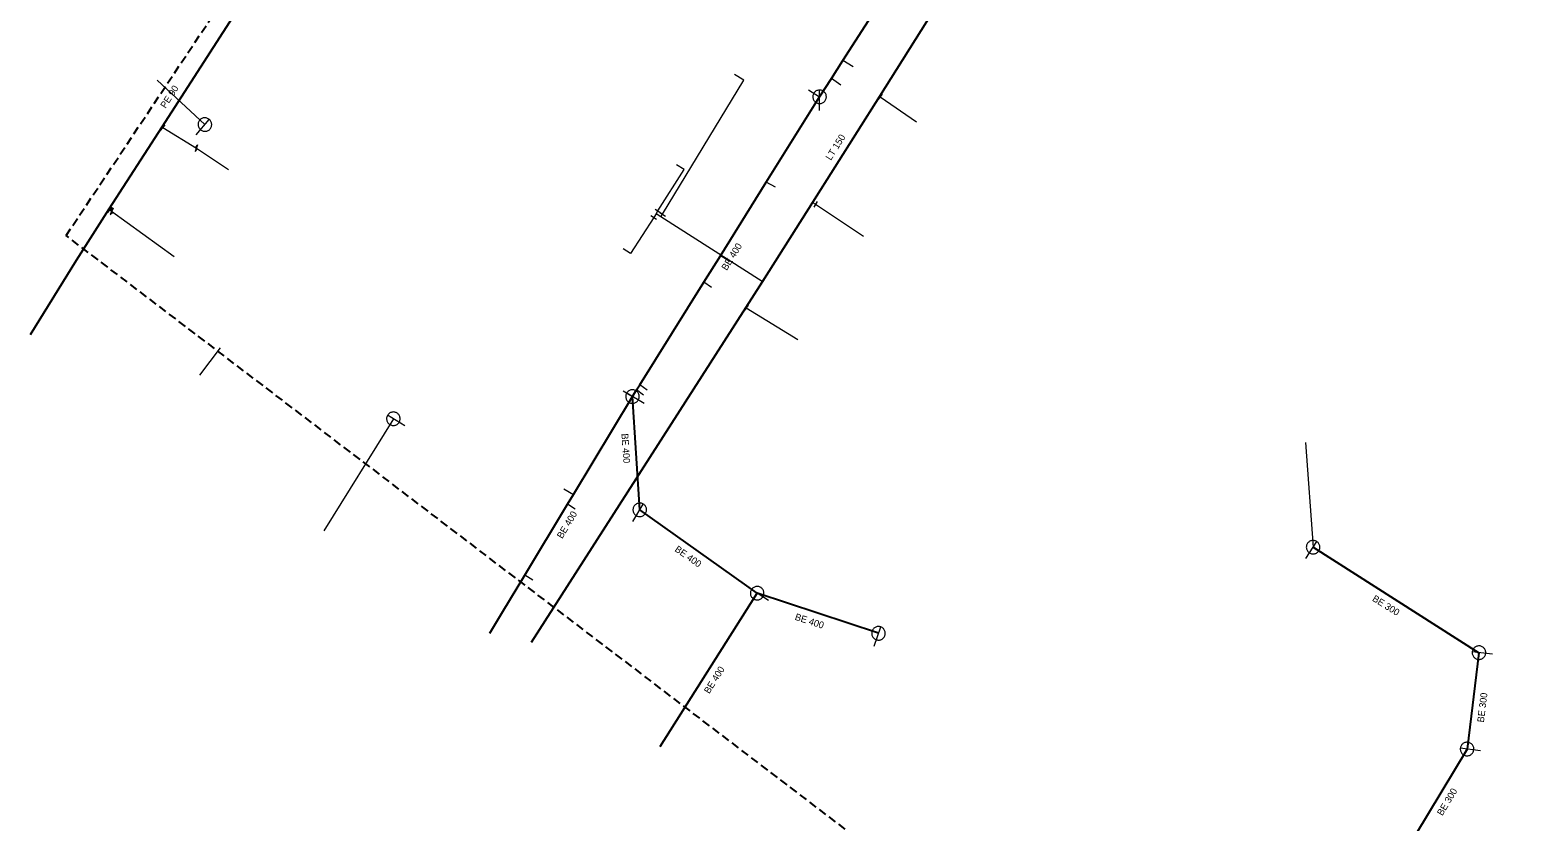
# Model space of a CAD drawing. Extents: x -791337 to -790755, y -988454 to -987923.
# Drawn here: x -791336.8 to -791114.4, y -988160.4 to -988043.6 of the extents above; entities that cross this region are included whole.
import ezdxf

# ---------------------------------------------------------------- set-up
doc = ezdxf.new("R2010")
doc.units = 0
doc.header["$LTSCALE"] = 0.4
doc.linetypes.add('MEDIUM_DASHED', pattern=[4.5, 3, -1.5])
for name, color, linetype, lineweight in [('1', 7, 'Continuous', 13), ('11', 7, 'Continuous', 13), ('13', 7, 'Continuous', 13), ('14', 7, 'Continuous', 25), ('17', 7, 'Continuous', 25), ('22', 7, 'Continuous', 13), ('34', 7, 'Continuous', 13), ('47', 7, 'Continuous', 13), ('63', 7, 'MEDIUM_DASHED', 25)]:
    doc.layers.add(name, color=color, linetype=linetype, lineweight=lineweight)

msp = doc.modelspace()

# ---------------------------------------------------------------- linework, layer by layer
at = {"layer": '11'}
for p, q in [((-791215.394, -988048.979), (-791216.914, -988048.035)), ((-791311.03, -988057.489), (-791318.067, -988050.953)), ((-791217.249, -988051.696), (-791218.616, -988050.685)), ((-791221.997, -988052.379), (-791220.36, -988053.399)), ((-791226.844, -988066.741), (-791228.219, -988065.989)), ((-791233.621, -988077.693), (-791234.99, -988076.837)), ((-791236.314, -988081.552), (-791237.428, -988080.744)), ((-791308.761, -988090.436), (-791311.837, -988094.46)), ((-791245.784, -988096.678), (-791246.89, -988095.902)), ((-791249.33, -988096.767), (-791247.96, -988097.618)), ((-791246.323, -988097.396), (-791247.349, -988096.637)), ((-791283.232, -988100.901), (-791293.503, -988117.455)), ((-791148.662, -988104.384), (-791147.564, -988119.853)), ((-791258.082, -988111.264), (-791256.681, -988112.097)), ((-791256.421, -988114.227), (-791257.529, -988113.506)), ((-791262.66, -988124.729), (-791263.835, -988123.978))]:
    msp.add_line(p, q, dxfattribs=at)
at = {"layer": '13'}
for p, q in [((-791211.439, -988053.409), (-791206.055, -988057.074)), ((-791220.971, -988069.259), (-791213.883, -988073.951)), ((-791244.489, -988070.666), (-791244.206, -988070.226)), ((-791231.17, -988084.549), (-791223.563, -988089.212))]:
    msp.add_line(p, q, dxfattribs=at)
for points in [[(-791243.519, -988070.729), (-791231.521, -988050.931), (-791232.905, -988050.09)], [(-791317.379, -988057.85), (-791317.26, -988057.94), (-791312.28, -988060.969), (-791307.574, -988064.107)], [(-791244.206, -988070.226), (-791240.35, -988064.101), (-791241.451, -988063.407)], [(-791325.199, -988069.989), (-791325.079, -988070.079), (-791324.794, -988070.282), (-791315.569, -988076.949)], [(-791244.831, -988071.195), (-791248.272, -988076.535), (-791249.34, -988075.846)], [(-791228.84, -988080.629), (-791243.759, -988071.116), (-791244.489, -988070.666), (-791244.831, -988071.195)]]:
    msp.add_lwpolyline(points, dxfattribs=at)
at = {"layer": '14', "lineweight": 13}
for p, q in [((-791211.533, -988053.348), (-791211.439, -988053.409)), ((-791221.417, -988069.009), (-791220.971, -988069.259)), ((-791243.759, -988071.116), (-791243.519, -988070.729)), ((-791228.785, -988080.667), (-791228.84, -988080.629)), ((-791231.254, -988084.482), (-791231.17, -988084.549))]:
    msp.add_line(p, q, dxfattribs=at)
at = {"layer": '14'}
for p, q in [((-791147.564, -988119.853), (-791123.093, -988135.415)), ((-791243.863, -988149.281), (-791229.566, -988126.639)), ((-791211.664, -988132.557), (-791229.566, -988126.639)), ((-791123.093, -988135.415), (-791124.854, -988149.635)), ((-791124.854, -988149.635), (-791132.46, -988162.294))]:
    msp.add_line(p, q, dxfattribs=at)
for points in [[(-791220.36, -988053.399), (-791218.616, -988050.685), (-791216.914, -988048.035), (-791206.587, -988031.96), (-791205.24, -988029.863), (-791199.047, -988020.224), (-791197.614, -988017.994), (-791194.219, -988012.71)], [(-791247.96, -988097.618), (-791247.349, -988096.637), (-791246.89, -988095.902), (-791237.428, -988080.744), (-791234.99, -988076.837), (-791228.219, -988065.989), (-791220.36, -988053.399)], [(-791268.993, -988132.543), (-791267.076, -988129.358), (-791263.835, -988123.978), (-791257.529, -988113.506), (-791256.681, -988112.097), (-791247.96, -988097.618)], [(-791229.566, -988126.639), (-791246.888, -988114.339), (-791247.96, -988097.618)]]:
    msp.add_lwpolyline(points, dxfattribs=at)
at = {"layer": '17'}
for points in [[(-791185.71, -988012.8), (-791199.495, -988034.364), (-791203.749, -988041.021), (-791211.533, -988053.348), (-791221.416, -988069.009), (-791228.785, -988080.667), (-791231.254, -988084.482), (-791262.91, -988133.899)], [(-791304.129, -988037.219), (-791317.379, -988057.85), (-791325.199, -988069.989), (-791330.01, -988077.55), (-791336.809, -988088.51)]]:
    msp.add_lwpolyline(points, dxfattribs=at)
at = {"layer": '22'}
for p, q in [((-791220.36, -988055.399), (-791220.359, -988052.399)), ((-791312.332, -988059.007), (-791310.379, -988056.73)), ((-791246.246, -988098.65), (-791248.816, -988097.102)), ((-791281.526, -988101.947), (-791284.083, -988100.378)), ((-791247.907, -988116.06), (-791246.378, -988113.478)), ((-791148.637, -988121.541), (-791147.027, -988119.009)), ((-791227.874, -988127.707), (-791230.411, -988126.105)), ((-791212.291, -988134.456), (-791211.35, -988131.608)), ((-791121.107, -988135.66), (-791124.084, -988135.292)), ((-791122.868, -988149.88), (-791125.845, -988149.512))]:
    msp.add_line(p, q, dxfattribs=at)
for points in [[(-791219.36, -988053.399), (-791219.365, -988053.29), (-791219.383, -988053.182), (-791219.413, -988053.076), (-791219.453, -988052.975), (-791219.505, -988052.878), (-791219.567, -988052.788), (-791219.639, -988052.705), (-791219.719, -988052.631), (-791219.807, -988052.565), (-791219.901, -988052.51), (-791220.001, -988052.465), (-791220.106, -988052.432), (-791220.213, -988052.41), (-791220.322, -988052.4), (-791220.432, -988052.402), (-791220.54, -988052.416), (-791220.647, -988052.441), (-791220.75, -988052.478), (-791220.848, -988052.527), (-791220.94, -988052.585), (-791221.026, -988052.654), (-791221.103, -988052.731), (-791221.172, -988052.817), (-791221.231, -988052.909), (-791221.279, -988053.007), (-791221.316, -988053.11), (-791221.342, -988053.217), (-791221.356, -988053.325), (-791221.359, -988053.435), (-791221.349, -988053.544), (-791221.328, -988053.651), (-791221.294, -988053.755), (-791221.25, -988053.855), (-791221.195, -988053.95), (-791221.129, -988054.038), (-791221.055, -988054.118), (-791220.972, -988054.19), (-791220.882, -988054.252), (-791220.786, -988054.304), (-791220.684, -988054.345), (-791220.579, -988054.375), (-791220.471, -988054.393), (-791220.361, -988054.399), (-791220.252, -988054.393), (-791220.144, -988054.375), (-791220.039, -988054.346), (-791219.937, -988054.305), (-791219.84, -988054.253), (-791219.75, -988054.191), (-791219.667, -988054.12), (-791219.592, -988054.04), (-791219.527, -988053.952), (-791219.471, -988053.858), (-791219.427, -988053.758), (-791219.393, -988053.654), (-791219.371, -988053.546), (-791219.361, -988053.437)], [(-791310.271, -988058.14), (-791310.204, -988058.053), (-791310.148, -988057.96), (-791310.101, -988057.86), (-791310.066, -988057.757), (-791310.042, -988057.649), (-791310.031, -988057.541), (-791310.031, -988057.431), (-791310.044, -988057.323), (-791310.068, -988057.215), (-791310.103, -988057.112), (-791310.15, -988057.013), (-791310.208, -988056.92), (-791310.275, -988056.833), (-791310.351, -988056.755), (-791310.436, -988056.685), (-791310.527, -988056.625), (-791310.625, -988056.574), (-791310.727, -988056.535), (-791310.833, -988056.509), (-791310.941, -988056.493), (-791311.051, -988056.489), (-791311.16, -988056.497), (-791311.268, -988056.518), (-791311.373, -988056.549), (-791311.473, -988056.592), (-791311.568, -988056.646), (-791311.658, -988056.711), (-791311.738, -988056.784), (-791311.812, -988056.866), (-791311.875, -988056.955), (-791311.929, -988057.05), (-791311.971, -988057.151), (-791312.002, -988057.256), (-791312.022, -988057.364), (-791312.03, -988057.473), (-791312.025, -988057.582), (-791312.009, -988057.691), (-791311.981, -988057.797), (-791311.942, -988057.899), (-791311.892, -988057.996), (-791311.831, -988058.087), (-791311.761, -988058.171), (-791311.682, -988058.247), (-791311.595, -988058.314), (-791311.501, -988058.37), (-791311.403, -988058.417), (-791311.299, -988058.452), (-791311.191, -988058.476), (-791311.082, -988058.487), (-791310.973, -988058.487), (-791310.864, -988058.475), (-791310.758, -988058.451), (-791310.654, -988058.416), (-791310.555, -988058.369), (-791310.462, -988058.312), (-791310.375, -988058.244), (-791310.296, -988058.168)], [(-791247.443, -988096.761), (-791247.54, -988096.71), (-791247.641, -988096.67), (-791247.748, -988096.641), (-791247.855, -988096.623), (-791247.965, -988096.617), (-791248.074, -988096.624), (-791248.182, -988096.643), (-791248.287, -988096.673), (-791248.389, -988096.715), (-791248.484, -988096.767), (-791248.574, -988096.829), (-791248.657, -988096.902), (-791248.731, -988096.982), (-791248.796, -988097.071), (-791248.851, -988097.166), (-791248.895, -988097.266), (-791248.928, -988097.37), (-791248.95, -988097.478), (-791248.958, -988097.587), (-791248.956, -988097.696), (-791248.941, -988097.805), (-791248.915, -988097.91), (-791248.877, -988098.014), (-791248.829, -988098.112), (-791248.77, -988098.204), (-791248.7, -988098.288), (-791248.622, -988098.366), (-791248.537, -988098.434), (-791248.444, -988098.492), (-791248.345, -988098.54), (-791248.243, -988098.577), (-791248.136, -988098.602), (-791248.028, -988098.615), (-791247.918, -988098.617), (-791247.808, -988098.606), (-791247.702, -988098.584), (-791247.597, -988098.55), (-791247.498, -988098.505), (-791247.404, -988098.45), (-791247.316, -988098.383), (-791247.236, -988098.309), (-791247.165, -988098.226), (-791247.103, -988098.135), (-791247.052, -988098.038), (-791247.012, -988097.936), (-791246.982, -988097.831), (-791246.965, -988097.723), (-791246.959, -988097.613), (-791246.966, -988097.504), (-791246.984, -988097.396), (-791247.014, -988097.291), (-791247.056, -988097.189), (-791247.107, -988097.093), (-791247.17, -988097.004), (-791247.242, -988096.921), (-791247.323, -988096.846), (-791247.411, -988096.782)], [(-791282.708, -988100.048), (-791282.804, -988099.997), (-791282.906, -988099.955), (-791283.012, -988099.926), (-791283.119, -988099.907), (-791283.228, -988099.9), (-791283.338, -988099.906), (-791283.446, -988099.924), (-791283.551, -988099.954), (-791283.653, -988099.994), (-791283.749, -988100.045), (-791283.84, -988100.107), (-791283.923, -988100.179), (-791283.998, -988100.259), (-791284.063, -988100.347), (-791284.119, -988100.441), (-791284.164, -988100.541), (-791284.198, -988100.645), (-791284.221, -988100.752), (-791284.23, -988100.861), (-791284.229, -988100.97), (-791284.215, -988101.08), (-791284.19, -988101.185), (-791284.152, -988101.289), (-791284.105, -988101.388), (-791284.046, -988101.48), (-791283.978, -988101.565), (-791283.9, -988101.643), (-791283.816, -988101.712), (-791283.723, -988101.771), (-791283.625, -988101.82), (-791283.523, -988101.858), (-791283.416, -988101.883), (-791283.308, -988101.898), (-791283.198, -988101.901), (-791283.089, -988101.89), (-791282.982, -988101.869), (-791282.877, -988101.836), (-791282.777, -988101.792), (-791282.683, -988101.737), (-791282.594, -988101.672), (-791282.514, -988101.598), (-791282.442, -988101.515), (-791282.379, -988101.425), (-791282.327, -988101.329), (-791282.286, -988101.227), (-791282.256, -988101.123), (-791282.238, -988101.014), (-791282.231, -988100.904), (-791282.237, -988100.795), (-791282.254, -988100.687), (-791282.283, -988100.581), (-791282.324, -988100.48), (-791282.375, -988100.383), (-791282.437, -988100.293), (-791282.508, -988100.21), (-791282.588, -988100.135), (-791282.676, -988100.069)], [(-791246.027, -988114.848), (-791245.977, -988114.752), (-791245.937, -988114.65), (-791245.909, -988114.543), (-791245.892, -988114.436), (-791245.887, -988114.326), (-791245.895, -988114.217), (-791245.915, -988114.109), (-791245.946, -988114.004), (-791245.988, -988113.903), (-791246.041, -988113.807), (-791246.104, -988113.718), (-791246.177, -988113.636), (-791246.258, -988113.562), (-791246.347, -988113.498), (-791246.443, -988113.444), (-791246.543, -988113.401), (-791246.647, -988113.368), (-791246.755, -988113.347), (-791246.864, -988113.339), (-791246.973, -988113.342), (-791247.082, -988113.358), (-791247.188, -988113.385), (-791247.291, -988113.424), (-791247.388, -988113.473), (-791247.48, -988113.533), (-791247.564, -988113.603), (-791247.641, -988113.681), (-791247.708, -988113.767), (-791247.766, -988113.861), (-791247.813, -988113.96), (-791247.849, -988114.063), (-791247.873, -988114.169), (-791247.886, -988114.278), (-791247.887, -988114.388), (-791247.875, -988114.497), (-791247.852, -988114.603), (-791247.817, -988114.708), (-791247.772, -988114.807), (-791247.715, -988114.901), (-791247.649, -988114.988), (-791247.574, -988115.067), (-791247.49, -988115.138), (-791247.398, -988115.199), (-791247.301, -988115.249), (-791247.199, -988115.289), (-791247.094, -988115.317), (-791246.985, -988115.334), (-791246.875, -988115.339), (-791246.766, -988115.331), (-791246.659, -988115.312), (-791246.554, -988115.282), (-791246.453, -988115.239), (-791246.357, -988115.187), (-791246.268, -988115.123), (-791246.186, -988115.051), (-791246.112, -988114.969), (-791246.048, -988114.881)], [(-791146.72, -988120.39), (-791146.667, -988120.294), (-791146.624, -988120.194), (-791146.592, -988120.088), (-791146.572, -988119.981), (-791146.564, -988119.872), (-791146.568, -988119.762), (-791146.584, -988119.654), (-791146.612, -988119.548), (-791146.65, -988119.445), (-791146.7, -988119.349), (-791146.76, -988119.257), (-791146.831, -988119.173), (-791146.91, -988119.097), (-791146.996, -988119.03), (-791147.09, -988118.972), (-791147.189, -988118.926), (-791147.293, -988118.89), (-791147.399, -988118.866), (-791147.508, -988118.855), (-791147.617, -988118.854), (-791147.727, -988118.866), (-791147.833, -988118.89), (-791147.937, -988118.926), (-791148.037, -988118.972), (-791148.13, -988119.028), (-791148.216, -988119.096), (-791148.296, -988119.172), (-791148.365, -988119.255), (-791148.426, -988119.347), (-791148.476, -988119.445), (-791148.516, -988119.546), (-791148.543, -988119.652), (-791148.559, -988119.76), (-791148.564, -988119.87), (-791148.556, -988119.979), (-791148.536, -988120.087), (-791148.505, -988120.192), (-791148.462, -988120.293), (-791148.409, -988120.388), (-791148.345, -988120.477), (-791148.272, -988120.559), (-791148.191, -988120.632), (-791148.101, -988120.696), (-791148.006, -988120.75), (-791147.905, -988120.792), (-791147.801, -988120.824), (-791147.693, -988120.844), (-791147.583, -988120.853), (-791147.474, -988120.849), (-791147.366, -988120.833), (-791147.26, -988120.806), (-791147.158, -988120.767), (-791147.06, -988120.717), (-791146.969, -988120.657), (-791146.885, -988120.587), (-791146.808, -988120.508), (-791146.741, -988120.421)], [(-791229.031, -988125.793), (-791229.127, -988125.74), (-791229.227, -988125.698), (-791229.333, -988125.666), (-791229.44, -988125.646), (-791229.55, -988125.639), (-791229.659, -988125.643), (-791229.767, -988125.659), (-791229.873, -988125.688), (-791229.976, -988125.727), (-791230.072, -988125.777), (-791230.164, -988125.837), (-791230.248, -988125.909), (-791230.323, -988125.987), (-791230.39, -988126.074), (-791230.447, -988126.168), (-791230.493, -988126.267), (-791230.529, -988126.371), (-791230.553, -988126.478), (-791230.563, -988126.587), (-791230.564, -988126.695), (-791230.551, -988126.805), (-791230.527, -988126.911), (-791230.491, -988127.015), (-791230.445, -988127.114), (-791230.388, -988127.207), (-791230.32, -988127.294), (-791230.244, -988127.373), (-791230.16, -988127.442), (-791230.068, -988127.503), (-791229.971, -988127.552), (-791229.869, -988127.592), (-791229.763, -988127.619), (-791229.655, -988127.635), (-791229.545, -988127.639), (-791229.435, -988127.63), (-791229.328, -988127.61), (-791229.223, -988127.579), (-791229.123, -988127.536), (-791229.027, -988127.482), (-791228.938, -988127.418), (-791228.857, -988127.345), (-791228.784, -988127.263), (-791228.72, -988127.174), (-791228.667, -988127.078), (-791228.625, -988126.977), (-791228.593, -988126.873), (-791228.573, -988126.765), (-791228.565, -988126.655), (-791228.57, -988126.546), (-791228.585, -988126.438), (-791228.613, -988126.332), (-791228.653, -988126.23), (-791228.702, -988126.132), (-791228.763, -988126.042), (-791228.833, -988125.957), (-791228.913, -988125.881), (-791229, -988125.814)], [(-791210.714, -988132.871), (-791210.686, -988132.765), (-791210.669, -988132.657), (-791210.664, -988132.547), (-791210.67, -988132.439), (-791210.689, -988132.33), (-791210.72, -988132.225), (-791210.762, -988132.124), (-791210.815, -988132.029), (-791210.878, -988131.938), (-791210.95, -988131.857), (-791211.031, -988131.783), (-791211.12, -988131.718), (-791211.215, -988131.664), (-791211.315, -988131.62), (-791211.42, -988131.587), (-791211.527, -988131.567), (-791211.636, -988131.557), (-791211.746, -988131.56), (-791211.854, -988131.576), (-791211.96, -988131.602), (-791212.063, -988131.64), (-791212.16, -988131.689), (-791212.253, -988131.749), (-791212.338, -988131.818), (-791212.414, -988131.896), (-791212.482, -988131.982), (-791212.54, -988132.076), (-791212.587, -988132.174), (-791212.623, -988132.278), (-791212.648, -988132.384), (-791212.662, -988132.492), (-791212.662, -988132.602), (-791212.652, -988132.711), (-791212.629, -988132.818), (-791212.594, -988132.922), (-791212.549, -988133.021), (-791212.493, -988133.116), (-791212.427, -988133.203), (-791212.352, -988133.283), (-791212.268, -988133.353), (-791212.178, -988133.415), (-791212.081, -988133.466), (-791211.978, -988133.506), (-791211.873, -988133.535), (-791211.765, -988133.551), (-791211.656, -988133.557), (-791211.546, -988133.55), (-791211.438, -988133.531), (-791211.333, -988133.5), (-791211.232, -988133.459), (-791211.136, -988133.407), (-791211.046, -988133.343), (-791210.964, -988133.272), (-791210.89, -988133.191), (-791210.826, -988133.103), (-791210.771, -988133.007), (-791210.727, -988132.907)], [(-791122.969, -988134.422), (-791123.078, -988134.415), (-791123.187, -988134.419), (-791123.296, -988134.436), (-791123.401, -988134.463), (-791123.504, -988134.503), (-791123.601, -988134.553), (-791123.692, -988134.615), (-791123.776, -988134.685), (-791123.852, -988134.764), (-791123.918, -988134.851), (-791123.975, -988134.944), (-791124.021, -988135.045), (-791124.056, -988135.148), (-791124.079, -988135.255), (-791124.09, -988135.364), (-791124.09, -988135.473), (-791124.078, -988135.583), (-791124.054, -988135.689), (-791124.017, -988135.793), (-791123.971, -988135.891), (-791123.913, -988135.985), (-791123.846, -988136.071), (-791123.77, -988136.15), (-791123.685, -988136.22), (-791123.594, -988136.279), (-791123.496, -988136.329), (-791123.393, -988136.368), (-791123.288, -988136.395), (-791123.179, -988136.41), (-791123.07, -988136.414), (-791122.961, -988136.406), (-791122.853, -988136.385), (-791122.749, -988136.354), (-791122.648, -988136.311), (-791122.552, -988136.256), (-791122.464, -988136.193), (-791122.382, -988136.119), (-791122.31, -988136.037), (-791122.246, -988135.949), (-791122.193, -988135.852), (-791122.15, -988135.752), (-791122.119, -988135.647), (-791122.1, -988135.538), (-791122.092, -988135.43), (-791122.097, -988135.32), (-791122.113, -988135.212), (-791122.141, -988135.106), (-791122.181, -988135.003), (-791122.231, -988134.907), (-791122.291, -988134.815), (-791122.361, -988134.731), (-791122.441, -988134.656), (-791122.527, -988134.589), (-791122.621, -988134.533), (-791122.72, -988134.486), (-791122.825, -988134.451), (-791122.932, -988134.428)], [(-791124.73, -988148.642), (-791124.839, -988148.635), (-791124.948, -988148.639), (-791125.057, -988148.656), (-791125.162, -988148.683), (-791125.265, -988148.723), (-791125.362, -988148.773), (-791125.453, -988148.835), (-791125.537, -988148.905), (-791125.613, -988148.984), (-791125.679, -988149.071), (-791125.736, -988149.164), (-791125.782, -988149.265), (-791125.817, -988149.368), (-791125.84, -988149.475), (-791125.851, -988149.584), (-791125.851, -988149.693), (-791125.839, -988149.803), (-791125.815, -988149.909), (-791125.778, -988150.013), (-791125.732, -988150.111), (-791125.674, -988150.205), (-791125.607, -988150.291), (-791125.531, -988150.37), (-791125.446, -988150.44), (-791125.355, -988150.499), (-791125.257, -988150.549), (-791125.154, -988150.588), (-791125.049, -988150.615), (-791124.94, -988150.63), (-791124.831, -988150.634), (-791124.722, -988150.626), (-791124.614, -988150.605), (-791124.51, -988150.574), (-791124.409, -988150.531), (-791124.313, -988150.476), (-791124.225, -988150.413), (-791124.143, -988150.339), (-791124.071, -988150.257), (-791124.007, -988150.169), (-791123.954, -988150.072), (-791123.911, -988149.972), (-791123.88, -988149.867), (-791123.861, -988149.758), (-791123.853, -988149.65), (-791123.858, -988149.54), (-791123.874, -988149.432), (-791123.902, -988149.326), (-791123.942, -988149.223), (-791123.992, -988149.127), (-791124.052, -988149.035), (-791124.122, -988148.951), (-791124.202, -988148.876), (-791124.288, -988148.809), (-791124.382, -988148.753), (-791124.481, -988148.706), (-791124.586, -988148.671), (-791124.693, -988148.648)]]:
    msp.add_lwpolyline(points, close=True, dxfattribs=at)
at = {"layer": '34'}
for p, q in [((-791211.148, -988053.002), (-791211.73, -988053.815)), ((-791316.96, -988057.539), (-791317.56, -988058.339)), ((-791324.779, -988069.678), (-791325.379, -988070.478)), ((-791220.726, -988068.822), (-791221.215, -988069.694)), ((-791245.251, -988070.923), (-791244.411, -988071.467)), ((-791244.626, -988069.956), (-791243.785, -988070.496)), ((-791243.944, -988070.466), (-791243.094, -988070.992)), ((-791228.571, -988080.207), (-791229.109, -988081.05)), ((-791230.878, -988084.143), (-791231.462, -988084.954))]:
    msp.add_line(p, q, dxfattribs=at)
at = {"layer": '47'}
for p, q in [((-791312.103, -988060.49), (-791312.451, -988060.864)), ((-791324.585, -988069.817), (-791324.958, -988070.166))]:
    msp.add_line(p, q, dxfattribs=at)
for points in [[(-791312.103, -988060.49), (-791312.456, -988061.447), (-791312.108, -988061.073)], [(-791324.585, -988069.817), (-791325.002, -988070.746), (-791324.629, -988070.397)]]:
    msp.add_lwpolyline(points, dxfattribs=at)
at = {"layer": '63'}
msp.add_lwpolyline([(-791231.02, -987923.132), (-790755.118, -988202.253), (-790755.118, -988202.253), (-790903.053, -988400.429), (-790903.053, -988400.429), (-791331.504, -988073.857), (-791331.504, -988073.857)], close=True, dxfattribs=at)

# ---------------------------------------------------------------- texts
at = {"layer": '1'}
for s, rotation, p in [('PE 90 ', 57, (-791316.845, -988055.174)), ('LT 150', 58, (-791218.701, -988062.853)), ('BE 400', 58, (-791234.064, -988079.104)), ('BE 400', 274, (-791249.597, -988103.111)), ('BE 400', 59, (-791258.324, -988118.673)), ('BE 400', 325, (-791241.822, -988120.37)), ('BE 300', 328, (-791138.925, -988127.7)), ('BE 400', 342, (-791224.086, -988130.542)), ('BE 400', 58, (-791236.637, -988141.556)), ('BE 300', 83, (-791122.372, -988145.746)), ('BE 300', 59, (-791128.5, -988159.559))]:
    msp.add_text(s, height=1, rotation=rotation, dxfattribs=at).set_placement(p)

doc.saveas('drawing.dxf')
